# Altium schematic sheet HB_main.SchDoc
size A4
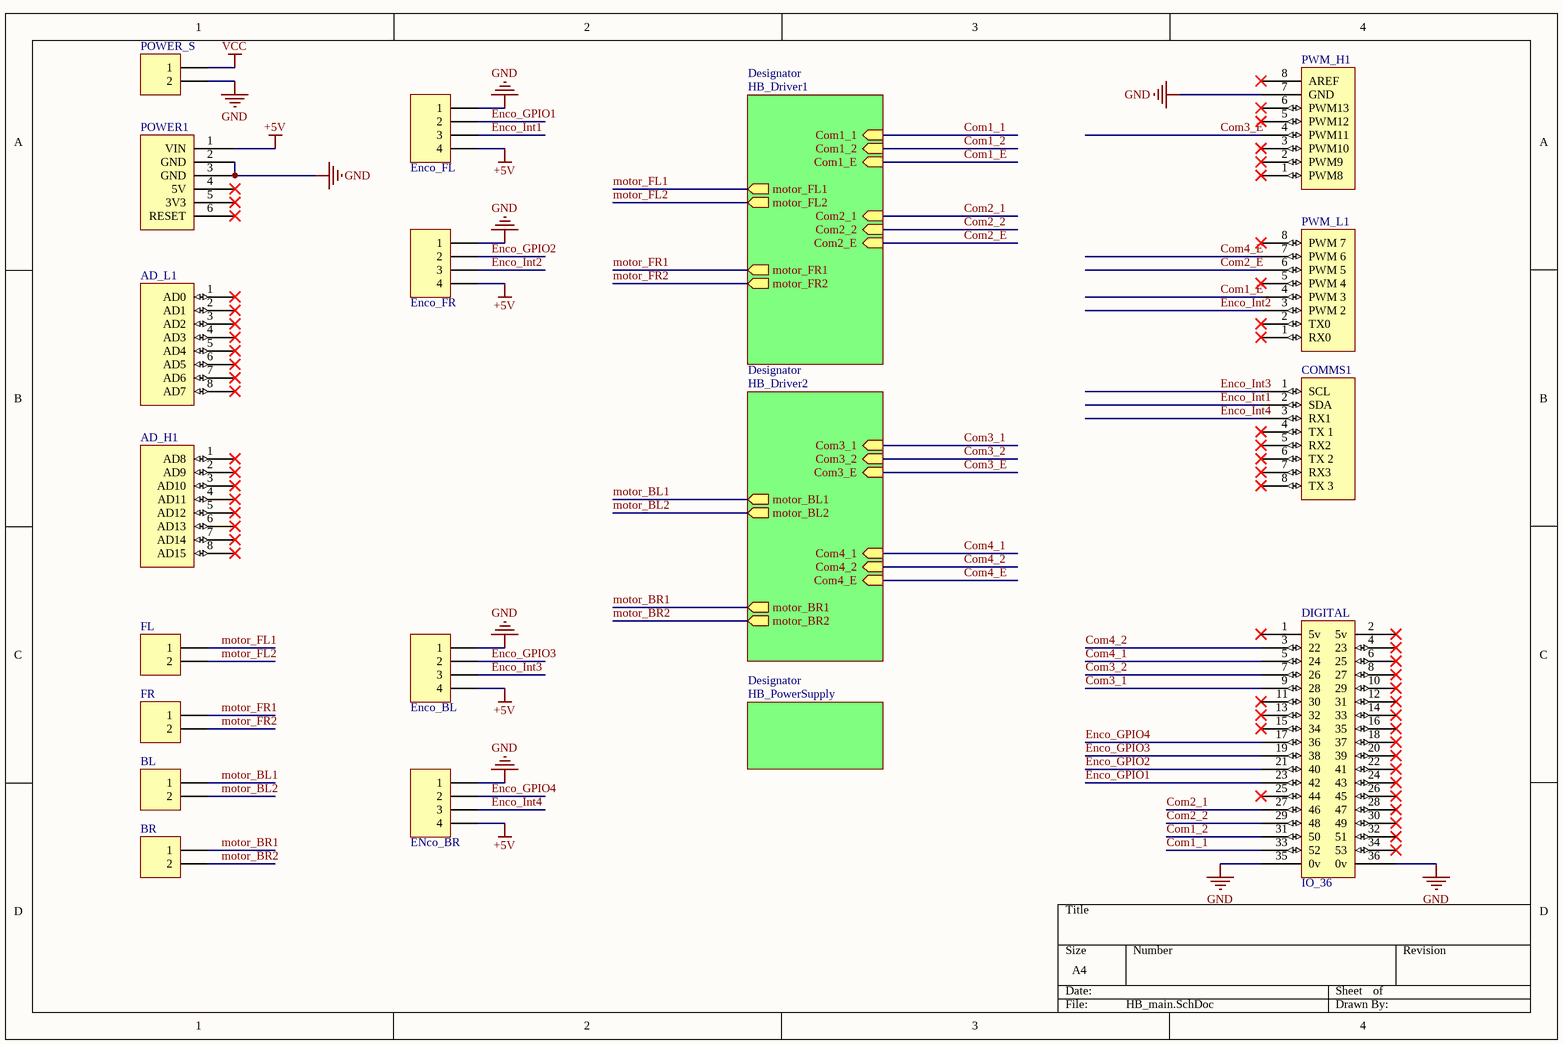
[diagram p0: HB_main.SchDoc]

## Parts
AD_H1  AD_H  [Header 8x1 8.5mm]  (value not drawn)
AD_L1  AD_L  [Header 8x1 8.5mm]  (value not drawn)
COMMS1  Communication  [Header 8x1 8.5mm]  (value not drawn)
DIGITAL  IO_36  [HEADER 36X 8MM]
J3  POWER_S  [Header_2]
J4  FL  [Header_2]
J5  FR  [Header_2]
J6  BL  [Header_2]
J7  BR  [Header_2]
P1  Enco_FL  [MOLEX_22-27-2081]
P2  Enco_FR  [MOLEX_22-27-2081]
P3  Enco_BL  [MOLEX_22-27-2081]
P4  ENco_BR  [MOLEX_22-27-2081]
POWER1  POWER  [Header 6x1 8.5mm]  (value not drawn)
PWM_H1  PWM_H  [Header 8x1 8.5mm]  (value not drawn)
PWM_L1  PWM_L  [Header 8x1 8.5mm]  (value not drawn)

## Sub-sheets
Designator = HB_Driver1: Com2_E (in), Com1_1 (in), Com1_E (in), Com1_2 (in), Com2_2 (in), Com2_1 (in), motor_FR2 (out), motor_FL1 (out), motor_FR1 (out), motor_FL2 (out)
Designator = HB_Driver2: Com4_1 (in), Com3_E (in), Com4_E (in), Com3_2 (in), Com4_2 (in), Com3_1 (in), motor_BL2 (out), motor_BR1 (out), motor_BR2 (out), motor_BL1 (out)
Designator = HB_PowerSupply: no entries

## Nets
+5V: P1.4 P2.4 P3.4 P4.4 POWER1.1(VIN)
GND: DIGITAL.35(0v) DIGITAL.36(0v) J3.2 P1.1 P2.1 P3.1 P4.1 POWER1.2(GND) POWER1.3(GND) PWM_H1.7(GND)
VCC: J3.1
Com1_1: DIGITAL.33(52) ; sheet Designator/Com1_1
Com1_2: DIGITAL.31(50) ; sheet Designator/Com1_2
Com1_E: PWM_L1.4(PWM_3) ; sheet Designator/Com1_E
Com2_1: DIGITAL.27(46) ; sheet Designator/Com2_1
Com2_2: DIGITAL.29(48) ; sheet Designator/Com2_2
Com2_E: PWM_L1.6(PWM_5) ; sheet Designator/Com2_E
Com3_1: DIGITAL.9(28) ; sheet Designator/Com3_1
Com3_2: DIGITAL.7(26) ; sheet Designator/Com3_2
Com3_E: PWM_H1.4(PWM11) ; sheet Designator/Com3_E
Com4_1: DIGITAL.5(24) ; sheet Designator/Com4_1
Com4_2: DIGITAL.3(22) ; sheet Designator/Com4_2
Com4_E: PWM_L1.7(PWM_6) ; sheet Designator/Com4_E
Enco_GPIO1: DIGITAL.23(42) P1.2
Enco_GPIO2: DIGITAL.21(40) P2.2
Enco_GPIO3: DIGITAL.19(38) P3.2
Enco_GPIO4: DIGITAL.17(36) P4.2
Enco_Int1: COMMS1.2(SDA) P1.3
Enco_Int2: P2.3 PWM_L1.3(PWM_2)
Enco_Int3: COMMS1.1(SCL) P3.3
Enco_Int4: COMMS1.3(RX1) P4.3
motor_BL1: J6.1 ; sheet Designator/motor_BL1
motor_BL2: J6.2 ; sheet Designator/motor_BL2
motor_BR1: J7.1 ; sheet Designator/motor_BR1
motor_BR2: J7.2 ; sheet Designator/motor_BR2
motor_FL1: J4.1 ; sheet Designator/motor_FL1
motor_FL2: J4.2 ; sheet Designator/motor_FL2
motor_FR1: J5.1 ; sheet Designator/motor_FR1
motor_FR2: J5.2 ; sheet Designator/motor_FR2

Not connected (* = marked no-connect by the designer): AD_H1 1(AD8)* 2(AD9)* 3(AD10)* 4(AD11)* 5(AD12)* 6(AD13)* 7(AD14)* 8(AD15)*; AD_L1 1(AD0)* 2(AD1)* 3(AD2)* 4(AD3)* 5(AD4)* 6(AD5)* 7(AD6)* 8(AD7)*; COMMS1 4(TX_1)* 5(RX2)* 6(TX_2)* 7(RX3)* 8(TX_3)*; DIGITAL 1(5v)* 2(5v)* 4(23)* 6(25)* 8(27)* 10(29)* 11(30)* 12(31)* 13(32)* 14(33)* 15(34)* 16(35)* 18(37)* 20(39)* 22(41)* 24(43)* 25(44)* 26(45)* 28(47)* 30(49)* 32(51)* 34(53)*; POWER1 4(5V)* 5(3V3)* 6(RESET)*; PWM_H1 1(PWM8)* 2(PWM9)* 3(PWM10)* 5(PWM12)* 6(PWM13)* 8(AREF)*; PWM_L1 1(RX0)* 2(TX0)* 5(PWM_4)* 8(PWM_7)*

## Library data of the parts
AD_H1 = AD_H: Header, 8-Pin
AD_L1 = AD_L: Header, 8-Pin
COMMS1 = Communication: Header, 8-Pin
DIGITAL = IO_36: Header, 36-Pin
J3-J7 = Connecteur 2: Connecteur
P1-P4 = Header 4: Header, 4-Pin
POWER1 = POWER: Header, 6-Pin
PWM_H1 = PWM_H: Header, 8-Pin
PWM_L1 = PWM_L: Header, 8-Pin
